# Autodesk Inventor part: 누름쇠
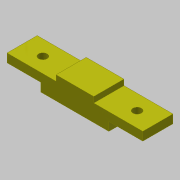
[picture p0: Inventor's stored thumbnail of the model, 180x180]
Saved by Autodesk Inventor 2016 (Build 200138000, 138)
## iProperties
Created: 2019-06
Part Number: 누름쇠
Material: 스테인리스강
Document SubType Name: Modeling
Designer: mduedu
Density: 1 g/cm^3
Appearance: 노란색
Author: mduedu
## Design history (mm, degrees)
sketch "스케치1"
  geometry: L1 (-36, 0)-(36, 0); L2 (36, 0)-(36, 12); L3 (36, 12)-(-36, 12); L4 (-36, 12)-(-36, 0); 2 further points
  constraints: 8 end point, 2 parallel, 1 coincident, 1 horizontal, 1 midpoint, 1 perpendicular
  dimensions: "d0" = 72 distance of L1.start L1.end; "d2" = 12 distance of L1.end L2.end
extrude "돌출1" new body sketch "스케치1" stored distance "d3" = 16; taper "d4" = 0 deg
sketch "스케치2"
  geometry: L1 (-36, 0)-(36, 0) reference; L2 (36, 0)-(36, 12) reference; L3 (36, 12)-(-36, 12) reference; L4 (-36, 12)-(-36, 0) reference; L5 (0, 0)-(0, 12); L6 (-36, 0)-(-18, 0); L7 (-18, 0)-(-18, 4.5); L8 (-18, 4.5)-(-36, 4.5); L9 (-36, 4.5)-(-36, 0); L10 (-36, 12)-(-10, 12); L11 (-10, 12)-(-10, 9); L12 (-10, 9)-(-36, 9); L13 (-36, 9)-(-36, 12); L14 (36, 12)-(36, 0); L15 (36, 0)-(18, 0); L16 (18, 0)-(18, 4.5); L17 (18, 4.5)-(36, 4.5); L18 (36, 4.5)-(36, 0); L19 (36, 12)-(10, 12); L20 (10, 12)-(10, 9); L21 (10, 9)-(36, 9); L22 (36, 9)-(36, 12)
  constraints: 36 end point, 6 symmetric about line, 4 parallel, 2 horizontal, 2 perpendicular, 1 midpoint
  dimensions: "d5" = 18 distance between parallel lines of L5 L7; "d7" = 4.5 distance between parallel lines of L1 L8; "d8" = 10 distance between parallel lines of L5 L11; "d9" = 3 distance between parallel lines of L12 L3
extrude "돌출2" cut sketch "스케치2" stored distance "d10" = 16; taper "d11" = 0 deg
sketch "스케치3"
  geometry: L1 (26, 0)-(26, 16) reference; L2 (0, 16)-(26, 16) reference; L3 (0, 0)-(0, 16) reference; L4 (26, 0)-(0, 0) reference; L5 (46, 0)-(26, 0) reference; L6 (46, 16)-(46, 0) reference; L7 (46, 16)-(72, 16) reference; L8 (72, 16)-(72, 0) reference; L9 (72, 0)-(46, 0) reference; L10 (26, 16)-(46, 16) reference; L11 (36, 16)-(36, 0); C1 r 2.25 at (11, 8); C2 r 2.25 at (61, 8); 1 further point
  constraints: 2 centre point, 2 end point, 2 midpoint, 1 horizontal alignment, 1 symmetric about line, 1 other
  dimensions: "d12" = 4.5 diameter of C1; "d13" = 25 distance of C1.centre point (36, 8)
extrude "돌출3" cut sketch "스케치3" stored distance "d14" = 16; taper "d15" = 0 deg
node "솔리드1"
node "투영된 루프1"
node "절단 모서리 투영1"
